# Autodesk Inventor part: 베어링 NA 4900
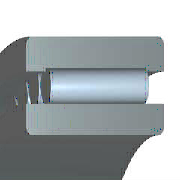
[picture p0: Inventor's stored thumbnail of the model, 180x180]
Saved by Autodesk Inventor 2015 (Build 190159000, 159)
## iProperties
Created: 2009-02
Part Number: 베어링 NA 4900
Material: 스테인리스강
Description: 니들 롤러 베어링 - 경계 치수 및 공차
Document SubType Name: Modeling
Standard: KS B 2029
Designer: SeoGD™
Standards Organization: KS
Language: ko-KR
Size Designation: NA 4900 - 10 x 22 x 13
Categories: <MemberInstance><Categories><Category DisplayName="샤프트 부품" InternalName="7f7aeb1f-a693-4053-b835-cee3144e0d98" Mnemonic="SHFT"><Category DisplayName="베어링" Inter
Density: 8.08 g/cm^3
Appearance: 반광택
Mass: 24.488 g
Surface Area: 38.613 cm^2
Volume: 3.0307 cm^3
IsCustomPart: 0
Author: SeoGD™
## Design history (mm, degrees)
sketch "스케치"
  geometry: L1 (1.857, 9)-(11.143, 9); L2 (11.143, 9)-(11.143, 7); L3 (13, 7)-(0, 7); L4 (1.857, 7)-(1.857, 9); L5 (1.857, 8)-(11.143, 8); L6 (6.5, 8)-(6.5, 7); L7 (0, 5)-(13, 5); L8 (0, 11)-(13, 11); L9 (13, 5)-(13, 7); L10 (13, 8.8)-(13, 11); L11 (1.857, 8.8)-(0, 8.8); L12 (11.143, 8.8)-(13, 8.8); L13 (-6, 0)-(36, 0) reference; L14 (0, -1.9)-(0, 14.9) reference
  constraints: 24 end point, 8 point on line, 3 midpoint, 3 parallel, 3 perpendicular, 2 symmetric about line, 1 horizontal, 1 other
  dimensions: "d6" = 10 diameter of L7 L13 (= WD); "d7" = 14 diameter of L3 L13 (= KID1); "d8" = 22 diameter of L8 L13 (= BD); "d9" = 16 diameter of L6.start L13 (= 0.5 x WD + 0.5 x BD); "d10" = 17.6 diameter of L12 L13 (= 0.9 x BD + 0.9 x WD - 0.8 x KID1); "d11" = 18 diameter of L1 L13 (= BD + WD - KID1); "d12" = 1.85714 distance between parallel lines of L14 L4 (= 0.142857 x KB); "d13" = 13 distance between parallel lines of L14 L9 (= KB); "d14" = 11.14286 distance between parallel lines of L14 L2 (= 0.857143 x KB)
revolve "본체" stored, may be unused: angle "d17" = 90 deg
revolve "롤러" stored, may be unused: angle "d18" = 90 deg
pattern_circular "IDS_ARRAYROLLER[SIMPL:T]" dims angle "d2" = 360 deg
body "Solid1"
fillet "모깎기1" dims "d0" = 0.3 (= KRS)
other parameters: "WD" = 10 [user parameter; used in 6 equation terms], "BD" = 22 [user parameter; used in 6 equation terms], "KB" = 13 [user parameter; used in 3 equation terms], "KID1" = 14 [user parameter; used in 4 equation terms], "KRS" = 0.3 [user parameter; used in 1 equation term], "d3" = 0, "d4" = 0, "d5" = 0, "d15" = 0, "d16" = 0, "BC0" = 9150000 [user parameter], "WR" = 5 (= 0.5 x WD) [user parameter], "BBA" = 0 [user parameter], "BC" = 8150000 [user parameter], "BR" = 11 (= 0.5 x BD) [user parameter]
